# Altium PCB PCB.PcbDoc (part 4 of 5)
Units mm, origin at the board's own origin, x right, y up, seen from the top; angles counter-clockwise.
Board outline 101.6 x 53.34 mm, 6 copper layers (Top Layer, Int1 (GND), Int2, Int3, Int4 (GND), Bottom Layer), stack 1.625 mm thick; 228 components, 228 nets, 1016 pads, 995 vias.
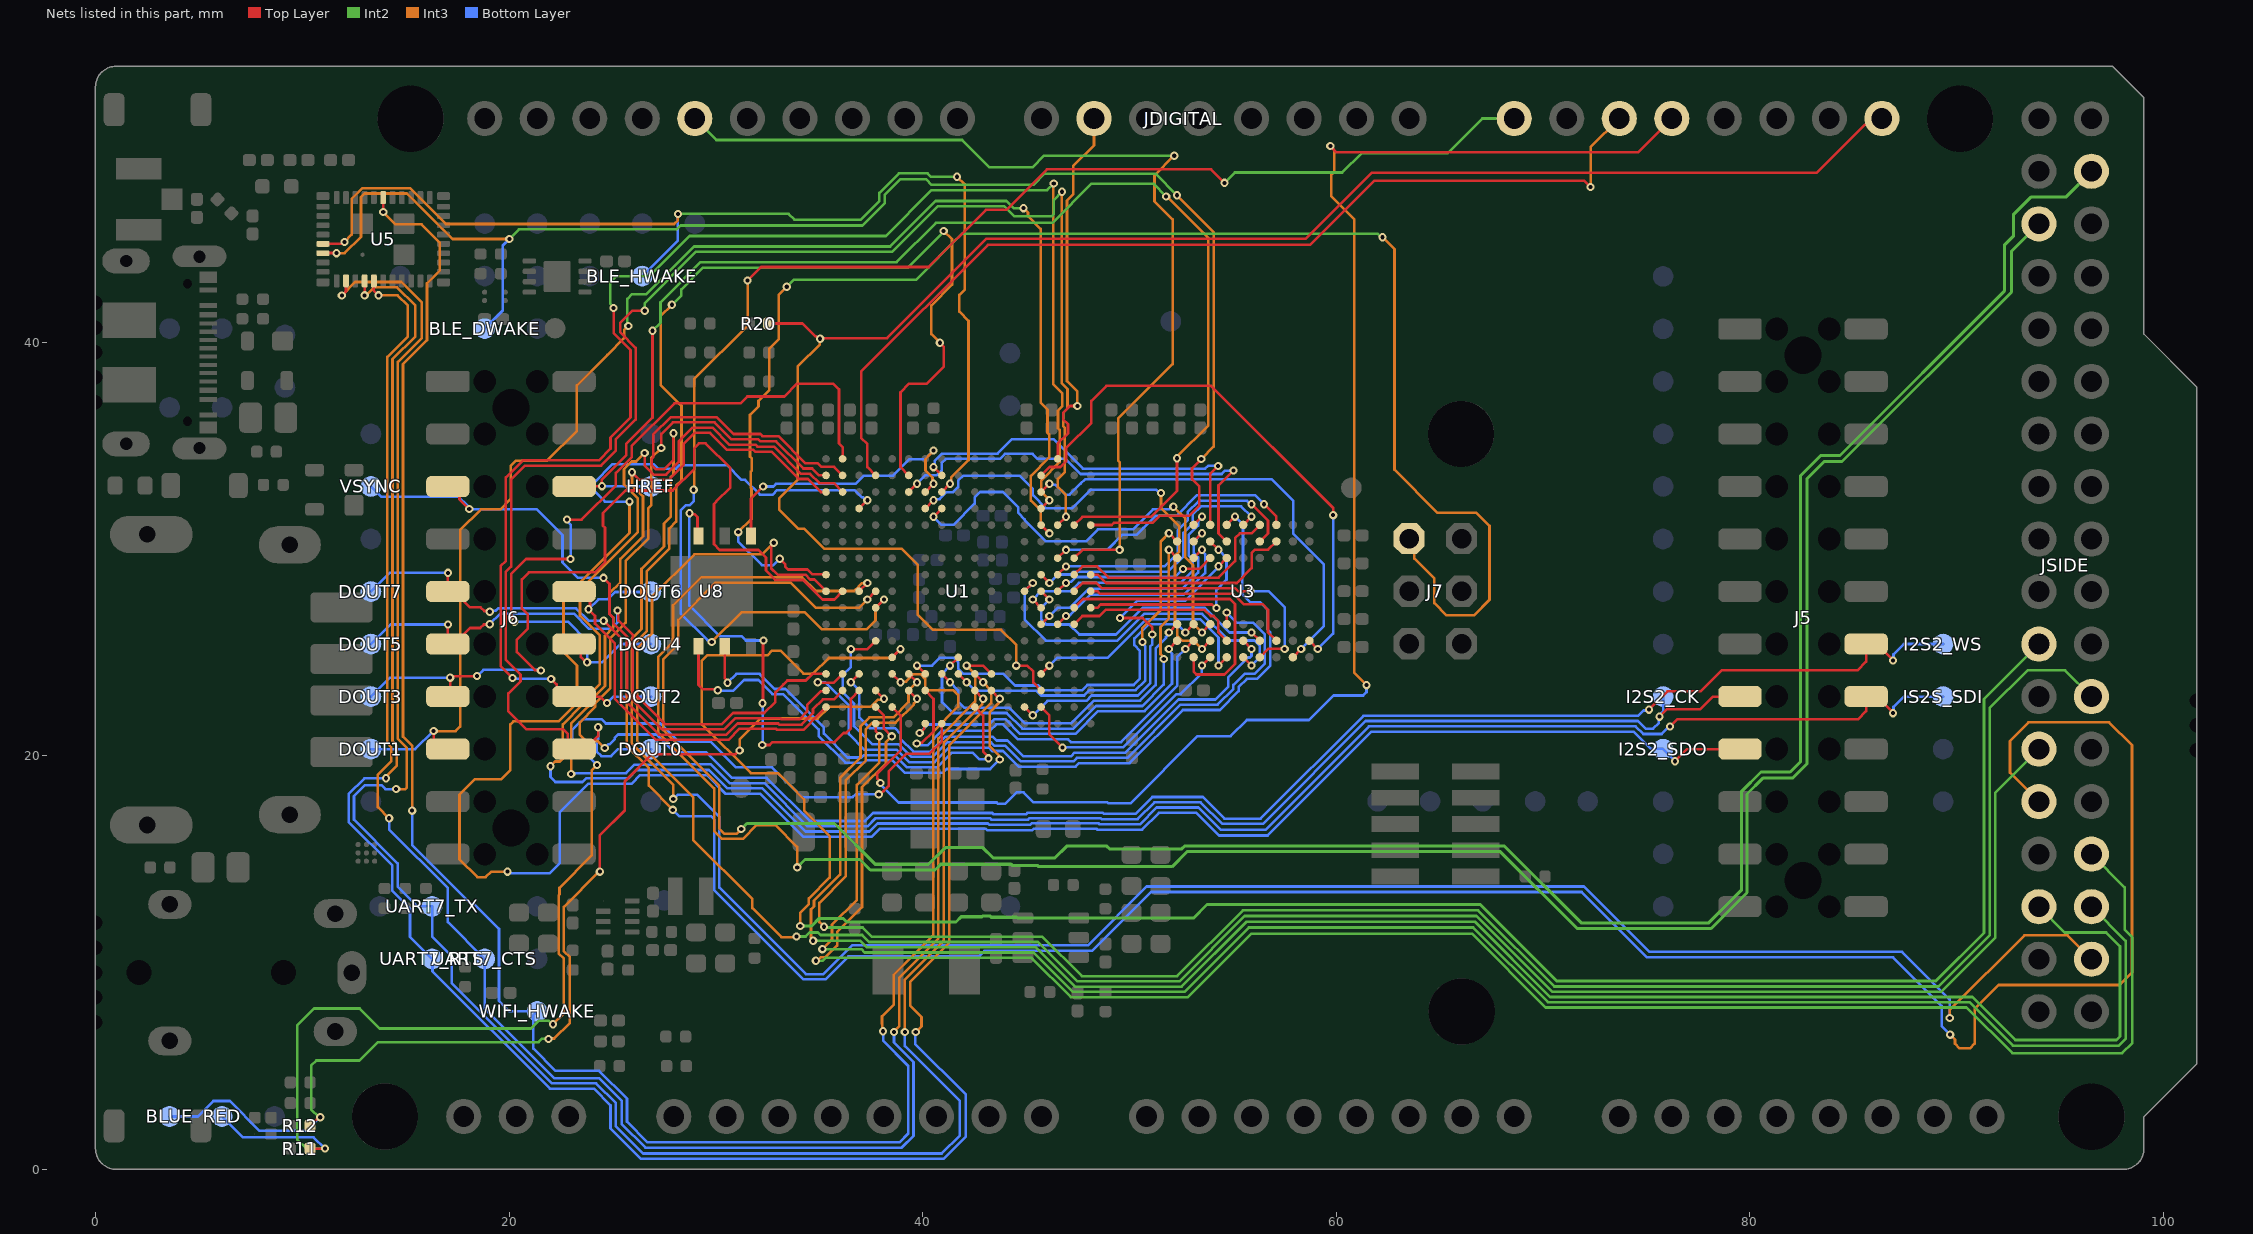
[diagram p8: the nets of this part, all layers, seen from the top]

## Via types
v1: diameter 0.4, hole 0.2, Top Layer to Bottom Layer, tented both sides, 995 vias

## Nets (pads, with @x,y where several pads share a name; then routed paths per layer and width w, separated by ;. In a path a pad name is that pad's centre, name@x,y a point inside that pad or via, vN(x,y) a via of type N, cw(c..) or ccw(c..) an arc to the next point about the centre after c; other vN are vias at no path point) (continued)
PD13: JDIGITAL.12 U1.R17 | length 18
  Top Layer w0.127: U1.R17@46.526,34.353 46.526,35.087 47.026,35.587 47.026,36.031 46.798,36.259 46.798,36.582 47.129,36.913 v1(47.482,36.913)
  Int3 w0.127: v1(47.482,36.913) 47.482,37.613 46.982,38.113 46.982,46.847 47.282,47.147 47.282,48.513 48.286,49.517 JDIGITAL.12@48.286,50.813
PD14_5: U1.P16 U3.A8 | length 27.1
  Top Layer w0.127: U1.P16@45.726,33.553 46.132,33.958 46.663,33.958 46.951,34.246 46.951,34.893 48.154,36.096 48.154,37.159 48.883,37.888 53.951,37.888 59.85,31.99 v1(59.85,31.633) ; U3.A8@58.704,25.56 v1(59.104,25.16)
  Bottom Layer w0.127: v1(59.104,25.16) 59.85,25.906 v1(59.85,31.633)
PD15_5: U1.P15 U3.B9 | length 22.1
  Top Layer w0.127: U1.P15@45.726,32.753 v1(46.126,33.153) ; U3.B9@57.904,24.76 v1(58.304,25.16)
  Bottom Layer w0.127: v1(46.126,33.153) 46.178,33.101 46.426,33.101 46.902,32.625 47.113,32.625 47.641,33.153 47.854,33.367 52.473,33.367 ; 52.473,33.366 56.881,33.366 57.913,32.334 57.913,30.747 59.404,29.257 59.404,26.26 v1(58.304,25.16)
PE0_5: U1.C4 U3.E8 | length 26.1
  Top Layer w0.127: v1(36.526,23.553) U1.C4@36.926,23.953 ; U3.E8@55.504,25.56 v1(55.904,25.16)
  Bottom Layer w0.127: v1(36.526,23.553) 36.936,23.144 36.936,21.84 37.441,21.334 38.658,21.334 38.936,21.056 38.936,20.817 39.555,20.198 40.374,20.198 41.098,20.921 43.384,20.921 43.571,20.734 44.104,20.734 44.859,19.98 47.187,19.98 47.354,20.147 49.799,20.147 52.372,22.72 54.161,22.72 54.773,23.332 54.773,23.781 55.742,24.75 55.829,24.75 55.904,24.825 v1(55.904,25.16)
PE1_5: U1.B4 U3.F1 | length 37.3
  Top Layer w0.127: v1(34.926,23.553) 34.951,23.528 35.702,23.528 U1.B4@36.126,23.953 ; U3.F1@54.704,31.16 v1(55.104,31.56)
  Bottom Layer w0.127: v1(34.926,23.553) 34.933,23.56 35.288,23.56 36.428,22.42 36.428,21.051 37.198,20.281 38.754,20.281 39.345,19.69 40.584,19.69 41.284,20.389 43.198,20.389 43.36,20.227 43.385,20.227 43.386,20.226 43.884,20.226 44.638,19.472 47.397,19.472 47.564,19.639 50.01,19.639 52.583,22.212 54.372,22.212 55.281,23.121 55.281,23.315 55.682,23.715 56.171,23.715 56.802,24.347 56.802,25.973 56.693,26.082 56.693,27.049 56.319,27.423 55.838,27.423 55.463,27.798 55.463,28.644 55.49,28.671 55.49,31.173 v1(55.104,31.56)
PE2_5: U1.C3 U8.3 | length 21.8
  Top Layer w0.127: v1(28.722,31.723) 28.774,31.67 28.982,31.67 29.113,31.54 29.113,30.671 U8.3@29.161,30.623 ; v1(32.242,20.515) 32.605,20.515 32.746,20.657 35.745,20.657 36.183,21.095 36.297,21.095 36.526,21.323 36.526,22.753 U1.C3@36.922,23.149 ; v1(32.259,22.539) 32.279,22.559 32.279,25.552 v1(32.3,25.572)
  Bottom Layer w0.127: v1(28.722,31.723) 28.722,27.257 30.206,25.773 31.252,25.773 31.453,25.572 v1(32.3,25.572) ; v1(32.242,20.515) 32.259,20.532 v1(32.259,22.539)
PE3: BLUE.X R12.2 U1.D3 | length 53.3
  Top Layer w0.127: R12.2@10.375,2.108 10.409,2.108 10.818,2.516 v1(10.867,2.516) ; v1(24.389,14.392) 24.389,16.154 25.594,17.36 25.594,18.745 26.919,20.071 30.958,20.071 31.138,20.25 v1(31.15,20.25) ; U1.D3@37.726,23.153 v1(38.126,22.753)
  Int2 w0.127: v1(10.867,2.516) 10.798,2.516 10.43,2.884 10.43,5.011 10.68,5.261 12.761,5.261 13.65,6.15 21.422,6.15 21.577,6.304 v1(21.904,6.304)
  Int3 w0.127: v1(21.904,6.304) 21.925,6.325 22.182,6.325 22.936,7.079 22.936,10.257 22.65,10.543 22.65,12.694 24.348,14.392 v1(24.389,14.392) ; v1(31.15,20.25) 31.15,20.792 32.157,21.798 34.922,21.798 35.486,22.362 37.488,22.362 37.827,22.701 38.075,22.701 v1(38.126,22.753)
  Bottom Layer w0.127: BLUE.X@3.582,2.553 4.953,2.553 5.7,3.3 6.5,3.3 7.938,1.862 10.213,1.862 v1(10.867,2.516)
PE4: JSIDE.30 U1.D2 | length 92.6
  Top Layer w0.127: U1.D2@37.726,22.353 38.126,21.953 38.126,21.314 v1(38.503,20.937)
  Int2 w0.127: v1(34.836,10.081) 35.163,10.081 35.31,10.227 45.26,10.227 47.165,8.323 52.823,8.323 55.897,11.397 66.555,11.397 70.128,7.825 90.48,7.825 92.689,5.615 98,5.615 98.5,6.115 98.5,11.215 98.126,11.589 98.126,13.633 JSIDE.30@96.52,15.239
  Int3 w0.127: v1(34.836,10.081) 34.909,10.081 35.082,10.254 35.312,10.254 35.868,10.811 35.868,11.473 37.068,12.673 37.068,18.476 38.226,19.635 38.226,20.66 v1(38.503,20.937)
PE5: JSIDE.32 U1.D1 | length 86.9
  Top Layer w0.127: U1.D1@37.726,21.553 37.726,21.185 37.903,21.008 v1(37.903,20.937)
  Int2 w0.127: v1(35.15,10.644) 37.036,10.644 37.199,10.481 45.366,10.481 47.27,8.577 52.658,8.577 55.775,11.693 66.619,11.693 70.233,8.079 90.617,8.079 92.72,5.976 97.84,5.976 98.177,6.312 98.177,11.042 JSIDE.32@96.52,12.699
  Int3 w0.127: v1(35.15,10.644) 35.614,11.109 35.614,11.829 36.814,13.029 36.814,18.581 37.903,19.671 v1(37.903,20.937)
PE6: JSIDE.21 U1.E5 | length 103.5
  Top Layer w0.127: U1.E5@38.526,24.753 v1(38.926,25.153)
  Int2 w0.15: v1(34.082,11.767) 34.631,11.767 34.995,12.131 36.149,12.131 36.322,11.958 41.609,11.958 41.863,12.211 42.868,12.211 42.914,12.258 43.247,12.258 43.317,12.188 44.536,12.188 44.579,12.144 53.095,12.144 53.752,12.801 66.964,12.801 70.652,9.113 89.005,9.113 91.322,11.429 91.322,22.74 JSIDE.21@93.98,25.399
  Int3 w0.127: v1(34.082,11.767) 34.082,12.409 34.492,12.818 34.492,13.098 35.5,14.106 35.5,16.109 34.271,17.338 34.271,17.888 33.933,18.226 33.933,18.236 33.109,19.059 33.099,19.059 33.001,19.158 31.691,19.158 29.311,21.537 29.311,24.591 29.576,24.856 32.5,24.856 32.723,25.079 33.127,25.079 34.236,23.97 34.708,23.97 35.461,24.723 38.496,24.723 v1(38.926,25.153)
PE7_5: U1.U9 U3.C8 | length 10.6
  Top Layer w0.127: U1.U9@48.126,27.953 48.445,27.953 48.562,27.836 55.017,27.836 55.522,27.331 56.423,27.331 56.699,27.055 56.699,25.964 U3.C8@57.104,25.56
PE8_5: U1.T9 U3.D9 | length 14.2
  Top Layer w0.127: U1.T9@47.326,27.953 47.726,28.353 48.217,28.353 48.404,28.353 48.667,28.09 55.122,28.09 55.253,27.96 v1(55.854,27.96) ; U3.D9@56.304,24.76 56.708,25.164 57.499,25.164 v1(57.504,25.16)
  Bottom Layer w0.127: v1(55.854,27.96) 56.723,27.96 57.512,27.171 57.512,25.168 v1(57.504,25.16)
PE9_5: U1.P9 U3.D8 | length 13.8
  Top Layer w0.127: U1.P9@45.726,27.953 v1(46.126,27.553) ; v1(55.904,25.96) U3.D8@56.304,25.56
  Bottom Layer w0.127: v1(46.126,27.553) 45.736,27.163 45.736,26.591 45.983,26.343 47.088,26.343 47.573,25.858 49.352,25.858 50.653,27.16 53.636,27.16 54.836,25.96 v1(55.904,25.96)
PE10_5: U1.N9 U3.E9 | length 17.1
  Top Layer w0.127: U1.N9@44.926,27.953 v1(45.326,28.353) ; U3.E9@55.504,24.76 v1(55.904,24.36)
  Bottom Layer w0.127: v1(45.326,28.353) 44.936,27.962 44.936,26.591 45.964,25.562 49.415,25.562 50.712,26.859 53.516,26.859 54.806,25.569 56.047,25.569 56.294,25.322 56.294,24.75 v1(55.904,24.36)
PE11_5: U1.P10 U3.E1 | length 13.6
  Top Layer w0.127: U1.P10@45.726,28.753 v1(46.126,28.353) ; U3.E1@55.504,31.16 v1(55.904,31.56)
  Bottom Layer w0.127: v1(46.126,28.353) 46.533,28.76 47.152,28.76 47.29,28.898 51.876,28.898 52.605,29.627 52.605,30.773 53.069,31.236 53.069,31.677 53.452,32.06 55.404,32.06 v1(55.904,31.56)
PE12_5: U1.R10 U3.D2 | length 14.1
  Top Layer w0.127: U1.R10@46.526,28.753 v1(46.926,29.153) ; v1(55.904,32.16) 56.699,31.364 56.699,30.755 U3.D2@56.304,30.36
  Bottom Layer w0.127: v1(46.926,29.153) 51.697,29.153 52.339,29.795 52.339,30.904 52.815,31.38 52.815,31.783 53.359,32.327 55.693,32.327 55.86,32.16 v1(55.904,32.16)
PE13_5: U1.T10 U3.D1 | length 11.1
  Top Layer w0.127: U1.T10@47.326,28.753 47.726,29.153 48.44,29.153 48.985,28.608 54.311,28.608 55.108,29.405 55.108,30.524 55.34,30.755 55.899,30.755 U3.D1@56.304,31.16
PE14_5: U1.U10 U3.C2 | length 10.4
  Top Layer w0.127: U1.U10@48.126,28.753 48.465,28.753 48.864,28.354 55.192,28.354 55.908,29.07 55.908,29.791 56.081,29.964 56.708,29.964 U3.C2@57.104,30.36
PE15_5: U1.R11 U3.C1 | length 12.7
  Top Layer w0.127: U1.R11@46.526,29.553 v1(46.926,29.953) ; v1(56.504,32.16) 57.104,31.56 U3.C1@57.104,31.16
  Bottom Layer w0.127: v1(46.926,29.953) 48.926,29.953 49.662,30.689 50.361,30.689 50.681,31.009 50.681,31.015 50.909,31.243 50.915,31.243 51.266,31.595 52.268,31.595 53.268,32.595 56.069,32.595 v1(56.504,32.16)
PF0_5: U1.G4 U3.H7 | length 18.1
  Top Layer w0.127: v1(39.726,24.353) U1.G4@40.126,23.953 ; v1(52.704,25.96) U3.H7@53.104,26.36
  Bottom Layer w0.127: v1(39.726,24.353) 40.449,24.353 40.839,24.743 41.488,24.743 41.728,24.504 41.728,24.199 41.967,23.96 43.904,23.96 44.466,23.397 45.593,23.397 45.828,23.162 47.703,23.162 47.961,23.42 50.199,23.42 50.505,23.726 50.505,25.072 50.236,25.341 50.236,25.665 50.549,25.978 ; 50.549,25.978 50.922,26.351 52.312,26.351 v1(52.704,25.96)
PF1_5: U1.G3 U3.H8 | length 20.2
  Top Layer w0.127: v1(39.717,20.588) 39.756,20.627 39.976,20.627 40.526,21.177 40.526,22.753 U1.G3@40.13,23.149 ; v1(52.704,25.16) U3.H8@53.104,25.56
  Bottom Layer w0.127: v1(39.717,20.588) 39.769,20.536 39.895,20.536 39.928,20.503 40.232,20.503 40.937,21.208 43.262,21.208 43.57,21.516 43.894,21.516 44.618,20.792 47.028,20.792 47.165,20.655 49.589,20.655 52.309,23.375 52.309,24.765 v1(52.704,25.16)
PF2_5: U1.G1 U3.J8 | length 16.7
  Top Layer w0.127: v1(39.855,21.1) 40.08,21.324 40.08,21.507 U1.G1@40.126,21.553 ; v1(51.904,25.16) U3.J8@52.304,25.56
  Bottom Layer w0.127: v1(39.855,21.1) 40.262,21.507 43.202,21.507 43.465,21.77 43.999,21.77 44.715,21.054 47.391,21.054 48.487,22.15 50.725,22.15 52.055,23.48 52.055,24.935 51.904,25.086 v1(51.904,25.16)
PF3_5: U1.H4 U3.J7 | length 15.8
  Top Layer w0.127: U1.H4@40.926,23.953 v1(41.326,23.553) ; v1(51.904,25.96) U3.J7@52.304,26.36
  Bottom Layer w0.127: v1(41.326,23.553) 41.717,23.162 41.717,22.61 42.007,22.32 44.184,22.32 44.942,21.562 47.181,21.562 48.276,22.658 50.515,22.658 51.267,23.411 51.267,25.191 51.768,25.692 51.768,25.75 51.904,25.886 v1(51.904,25.96)
PF4_5: U1.J5 U3.J3 | length 21.9
  Top Layer w0.127: v1(41.326,24.353) U1.J5@41.726,24.753 ; v1(51.904,29.96) U3.J3@52.304,29.56
  Int3 w0.127: v1(51.658,24.679) 51.658,24.753 51.498,24.912 51.498,26.219 51.904,26.624 v1(51.904,29.96)
  Bottom Layer w0.127: v1(41.326,24.353) 40.936,23.962 40.936,22.591 41.461,22.066 44.062,22.066 44.82,21.308 47.286,21.308 48.381,22.404 50.62,22.404 51.658,23.442 v1(51.658,24.679)
PF5_5: U1.J4 U3.J2 | length 18
  Top Layer w0.127: U1.J4@41.726,23.953 v1(42.126,23.553) ; v1(51.904,30.76) U3.J2@52.304,30.36
  Int3 w0.127: v1(50.626,25.503) 50.626,26.169 51.513,27.056 51.513,30.369 v1(51.904,30.76)
  Bottom Layer w0.127: v1(42.126,23.553) 42.536,23.143 45.488,23.143 45.723,22.908 47.808,22.908 48.066,23.166 50.304,23.166 50.759,23.621 50.759,25.296 50.626,25.429 v1(50.626,25.503)
PF6_5: U1.K2 U8.7 | length 19.9
  Top Layer w0.127: U8.7@30.431,25.283 30.431,23.74 30.567,23.604 v1(30.567,23.531) ; U1.K2@42.526,22.353 42.926,21.953 42.926,20.203 43.189,19.94 v1(43.189,19.871)
  Bottom Layer w0.127: v1(30.567,23.531) 30.997,23.961 32.111,23.961 32.844,23.228 33.362,23.228 35.221,21.369 35.221,21.066 36.372,19.915 37.044,19.915 37.156,20.027 38.64,20.027 39.231,19.436 40.69,19.436 41.389,20.135 42.431,20.135 42.735,19.83 43.149,19.83 v1(43.189,19.871)
PF7: U1.K3 U5.2 UART7_TX.X | length 97.1
  Top Layer w0.127: v1(11.914,42.258) 12.115,42.458 U5.2@12.115,42.96 ; U1.K3@42.526,23.153 v1(42.926,22.753)
  Int3 w0.127: v1(11.914,42.258) 12.562,42.905 14.795,42.905 15.78,41.92 15.78,40.197 14.62,39.036 14.62,20.816 15.058,20.378 15.058,18.459 14.983,18.384 v1(14.54,18.384) ; v1(39.139,6.634) 39.139,9.167 41.025,11.054 41.025,20.641 42.882,22.499 42.882,22.709 v1(42.926,22.753)
  Bottom Layer w0.127: v1(14.54,18.384) 14.021,18.384 13.83,18.575 13.025,18.575 12.5,18.049 12.5,16.907 14.613,14.794 14.613,13.676 15.577,12.713 UART7_TX.X@16.282,12.713 16.282,11.247 17.222,10.307 17.222,9.008 22.075,4.154 24.21,4.154 25.165,3.199 25.165,2.079 26.479,0.765 40.918,0.765 41.794,1.642 41.794,3.306 39.139,5.961 v1(39.139,6.634)
PF8: U1.K4 U5.4 UART7_RTS.X | length 96
  Top Layer w0.127: v1(13.015,42.26) U5.4@13.015,42.96 ; U1.K4@42.526,23.953 v1(42.926,23.553)
  Int3 w0.127: v1(13.015,42.26) 13.089,42.26 13.48,42.651 14.581,42.651 15.466,41.767 15.466,40.274 14.366,39.174 14.366,20.711 14.564,20.513 14.564,19.508 14.155,19.1 14.155,19.09 14.048,18.983 v1(14.048,18.909) ; v1(39.666,6.634) 39.947,6.916 39.947,7.362 39.393,7.916 39.393,9.062 41.279,10.948 41.279,20.501 43.317,22.538 43.317,23.162 v1(42.926,23.553)
  Bottom Layer w0.127: v1(14.048,18.909) 13.001,18.909 12.246,18.154 12.246,16.802 14.359,14.689 14.359,13.463 15.21,12.612 15.21,11.244 16.298,10.157 16.298,9.573 21.97,3.9 24.1,3.9 24.908,3.092 24.908,1.972 26.372,0.508 41.02,0.508 42.092,1.58 42.092,3.608 39.637,6.063 39.637,6.605 v1(39.666,6.634)
PF9: U1.L4 U5.5 UART7_CTS.X | length 90
  Top Layer w0.127: U5.5@13.465,42.96 13.465,42.481 v1(13.686,42.26) ; v1(42.126,24.353) 42.926,24.353 U1.L4@43.326,23.953
  Int3 w0.127: v1(13.686,42.26) 14.613,42.26 15.109,41.765 15.109,40.276 14.112,39.279 14.112,20.606 14.31,20.408 14.31,19.732 13.658,19.08 13.658,17.517 v1(14.2,16.975) ; v1(38.612,6.634) 38.612,6.66 38.874,6.921 38.874,9.277 40.76,11.163 40.76,20.835 42.536,22.61 42.536,23.943 v1(42.126,24.353)
  Bottom Layer w0.127: v1(14.2,16.975) 14.2,16.433 17.037,13.596 17.037,11.957 UART7_CTS.X@18.822,10.173 18.822,7.767 22.181,4.408 24.353,4.408 25.446,3.315 25.446,2.195 26.595,1.046 38.989,1.046 39.557,1.614 39.557,5.184 38.612,6.129 v1(38.612,6.634)
PF10_5: U1.L3 U8.6 | length 23
  Top Layer w0.127: U8.6@29.161,25.283 29.161,24.158 29.161,23.424 29.365,23.22 30.038,23.22 v1(30.09,23.167) ; U1.L3@43.326,23.153 v1(43.726,22.753)
  Int3 w0.127: v1(43.726,19.815) 43.674,19.867 43.674,20.027 43.245,20.456 43.245,22.108 43.674,22.536 43.674,22.701 v1(43.726,22.753)
  Bottom Layer w0.127: v1(30.09,23.167) 30.118,23.14 30.835,23.14 31.358,23.663 32.05,23.663 32.739,22.974 33.257,22.974 34.967,21.264 34.967,20.961 36.267,19.661 37.178,19.661 37.29,19.773 38.534,19.773 39.126,19.182 40.986,19.182 41.158,19.354 43.265,19.354 v1(43.726,19.815)
PF11_5: U1.T7 U3.F8 | length 8.6
  Top Layer w0.127: U1.T7@47.326,26.353 47.726,26.753 48.547,26.753 48.85,27.056 53.636,27.056 53.937,26.755 54.068,26.755 54.299,26.524 54.299,25.964 U3.F8@54.704,25.56
PF12_5: U1.R7 U3.H3 | length 9.9
  Top Layer w0.127: U1.R7@46.526,26.353 v1(46.926,26.753) ; U3.H3@53.104,29.56 v1(53.504,29.96)
  Bottom Layer w0.127: v1(46.926,26.753) 46.978,26.805 47.129,26.805 48.103,27.779 52.61,27.779 53.659,28.828 53.659,29.749 53.504,29.904 v1(53.504,29.96)
PF13_5: U1.P7 U3.H2 | length 11.4
  Top Layer w0.127: U1.P7@45.726,26.353 v1(46.126,26.753) ; U3.H2@53.104,30.36 v1(53.504,30.76)
  Bottom Layer w0.127: v1(46.126,26.753) 46.533,27.16 47.124,27.16 48.03,28.066 52.538,28.066 53.326,28.854 53.326,29.586 53.113,29.798 53.113,30.369 v1(53.504,30.76)
PF14_5: U1.P8 U3.H1 | length 12.4
  Top Layer w0.127: v1(45.326,27.553) U1.P8@45.726,27.153 ; U3.H1@53.104,31.16 v1(53.504,31.56)
  Bottom Layer w0.127: v1(45.326,27.553) 45.726,27.953 47.149,27.953 47.557,28.361 52.474,28.361 53.061,28.948 53.061,29.491 52.859,29.693 52.859,30.668 53.323,31.131 53.323,31.316 53.504,31.497 v1(53.504,31.56)
PF15_5: U1.R9 U3.G3 | length 8
  Top Layer w0.127: U1.R9@46.526,27.953 v1(46.926,28.353) ; v1(52.593,29.032) 53.376,29.032 U3.G3@53.904,29.56
  Bottom Layer w0.127: v1(46.926,28.353) 46.978,28.405 47.169,28.405 47.408,28.644 52.204,28.644 v1(52.593,29.032)
PG0_5: U1.T8 U3.H9 | length 13.9
  Top Layer w0.127: U1.T8@47.326,27.153 47.751,27.577 54.855,27.577 55.103,27.33 55.103,24.441 54.587,23.926 53.238,23.926 53.104,24.06 U3.H9@53.104,24.76
PG1_5: U1.U8 U3.G2 | length 10
  Top Layer w0.127: U1.U8@48.126,27.153 48.45,27.153 48.607,27.31 53.994,27.31 54.161,27.143 v1(54.205,27.143) ; U3.G2@53.904,30.36 v1(54.304,29.96)
  Bottom Layer w0.127: v1(54.205,27.143) 54.205,28.025 54.694,28.514 54.694,29.569 v1(54.304,29.96)
PG2_5: U1.H16 U3.G1 | length 18.7
  Top Layer w0.127: v1(40.526,33.953) U1.H16@40.926,33.553 ; U3.G1@53.904,31.16 53.904,33.626 v1(54.289,34.011)
  Bottom Layer w0.127: v1(40.526,33.953) 40.578,34.005 40.578,34.253 40.935,34.61 43.624,34.61 44.323,35.309 46.316,35.309 47.749,33.876 53.665,33.876 53.805,34.016 54.283,34.016 v1(54.289,34.011)
PG3: BLE_HWAKE.X U1.H15 U5.38 | length 55.2
  Top Layer w0.127: U5.38@11,44.75 11.872,44.75 11.963,44.841 v1(12.037,44.841) ; U1.H15@40.926,32.753 v1(41.326,33.153)
  Int2 w0.127: v1(28.165,46.2) 33.515,46.2 33.797,45.918 37.008,45.918 37.906,46.816 37.906,47.22 38.849,48.163 40.238,48.163 40.407,47.994 v1(41.664,47.994)
  Int3 w0.127: v1(12.037,44.841) 12.388,45.192 12.388,46.919 12.912,47.442 15.212,47.442 16.945,45.709 27.983,45.709 28.165,45.891 v1(28.165,46.2) ; v1(41.326,33.153) 41.378,33.205 41.378,33.453 42.216,34.291 42.216,41.025 41.77,41.471 41.77,42.277 42.036,42.543 42.036,47.622 v1(41.664,47.994)
  Bottom Layer w0.127: BLE_HWAKE.X@26.442,43.193 28.165,44.916 v1(28.165,46.2)
PG4_5: U1.H14 U3.G7 | length 22.2
  Top Layer w0.127: v1(40.526,31.553) U1.H14@40.926,31.953 ; v1(53.504,25.96) U3.G7@53.904,26.36
  Int3 w0.127: v1(52.122,32.036) 52.698,31.46 52.698,29.592 53.075,29.215 53.075,26.389 v1(53.504,25.96)
  Bottom Layer w0.127: v1(40.526,31.553) 40.917,31.162 41.488,31.162 42.517,32.191 42.517,32.496 42.774,32.753 43.878,32.753 44.626,32.005 44.626,31.741 44.936,31.432 44.936,31.391 45.964,30.362 47.888,30.362 48.469,30.943 50.166,30.943 51.135,31.912 51.924,31.912 52.048,32.036 v1(52.122,32.036)
PG5_5: U1.G14 U3.G8 | length 22.9
  Top Layer w0.127: U1.G14@40.126,31.953 v1(40.526,32.353) ; v1(53.504,25.16) U3.G8@53.904,25.56
  Int3 w0.127: v1(51.526,32.703) 51.526,31.97 52.408,31.087 52.408,29.885 52.202,29.679 52.202,26.334 52.313,26.223 52.313,25.798 52.561,25.55 53.113,25.55 v1(53.504,25.16)
  Bottom Layer w0.127: v1(40.526,32.353) 40.578,32.405 40.826,32.405 41.164,32.743 41.469,32.743 41.717,32.991 41.717,33.296 41.964,33.543 44.688,33.543 45.326,32.905 45.326,32.601 45.964,31.962 46.298,31.962 47.215,31.962 48.111,32.859 51.297,32.859 51.452,32.703 v1(51.526,32.703)
PG6_5: U1.G15 U8.1 | length 14.1
  Top Layer w0.127: U8.1@31.701,30.623 31.701,31.748 ; 31.7,31.748 31.7,32.431 v1(32.286,33.017) ; U1.G15@40.126,32.753 v1(40.526,33.153)
  Int3 w0.127: v1(40.526,33.153) 40.474,33.205 40.474,33.453 40.136,33.791 40.136,34.347 40.278,34.489 40.278,34.504 v1(40.526,34.753)
  Bottom Layer w0.127: v1(32.286,33.017) 32.785,33.017 32.91,33.142 36.763,33.142 37.164,33.543 38.573,33.543 39.373,34.343 40.117,34.343 v1(40.526,34.753)
PG7: JSIDE.34 U1.F16 | length 136.9
  Top Layer w0.127: U1.F16@39.326,33.553 38.926,33.953 38.926,37.571 39.343,37.988 40.201,37.988 41.016,38.803 41.016,39.782 v1(40.831,39.969) v1(40.831,39.969)
  Int2 w0.127: v1(27.873,41.804) 28.329,42.26 28.329,42.541 29.387,43.599 39.283,43.599 41.016,45.331 v1(41.016,45.378)
  Int3 w0.127: 26.301,25.663 25.936,25.298 25.936,20.578 27.942,18.573 v1(27.942,17.913) ; 26.301,25.664 26.66,26.022 26.66,28.928 27.748,30.015 27.748,30.996 28.077,31.326 28.077,33.054 28.339,33.316 28.339,36.914 27.328,37.925 27.328,41.259 v1(27.873,41.804) ; v1(40.831,39.969) 40.416,40.384 40.416,41.778 41.416,42.778 41.416,44.978 v1(41.016,45.378) ; v1(89.666,7.313) 89.666,7.699 93.276,11.31 95.369,11.31 JSIDE.34@96.52,10.159
  Bottom Layer w0.127: v1(27.942,17.913) 27.961,17.913 28.152,18.105 29.102,18.105 30.168,17.038 30.168,13.618 34.35,9.437 35.199,9.437 36.593,10.83 47.986,10.83 50.833,13.677 71.978,13.677 75.138,10.516 87.357,10.516 89.666,8.207 v1(89.666,7.313)
PG8_5: U1.F15 U3.F2 | length 21
  Top Layer w0.127: U1.F15@39.326,32.753 v1(39.726,33.153) ; U3.F2@54.704,30.36 54.308,30.755 54.308,33.07 v1(55.026,33.788)
  Bottom Layer w0.127: v1(39.726,33.153) 40.136,33.562 40.688,33.562 40.917,33.791 40.917,34.155 41.117,34.356 43.729,34.356 43.971,34.597 45.32,34.597 45.562,34.356 46.911,34.356 47.644,33.622 52.576,33.622 52.579,33.62 54.456,33.62 54.624,33.788 v1(55.026,33.788)
PG9: J7.1 U1.A10 | length 76.2
  Top Layer w0.127: v1(33.093,29.526) 33.354,29.265 33.354,29.146 33.494,29.006 34.432,29.006 34.665,28.772 35.307,28.772 U1.A10@35.326,28.753
  Int2 w0.127: v1(33.429,42.68) 33.764,43.014 39.667,43.014 41.894,45.241 61.999,45.241 62.168,45.073 v1(62.242,45.073)
  Int3 w0.127: v1(31.081,30.809) 31.721,31.449 31.721,32.942 31.683,32.979 31.683,33.738 31.736,33.79 31.736,34.378 31.652,34.462 31.652,36.481 32.062,36.891 32.062,37.156 32.584,37.677 32.584,39.689 33.047,40.152 33.047,42.297 v1(33.429,42.68) ; v1(62.242,45.073) 62.817,44.497 62.817,33.831 64.903,31.745 66.776,31.745 67.41,31.111 67.41,27.541 66.652,26.783 65.331,26.783 64.742,27.373 64.742,28.573 63.779,29.535 63.779,30.239 J7.1@63.526,30.493
  Bottom Layer w0.127: v1(31.081,30.809) 31.081,30.358 32.228,29.211 32.777,29.211 v1(33.093,29.526)
PG10: JSIDE.25 U1.A9 | length 104.7
  Top Layer w0.127: v1(32.8,30.3) 32.8,30.226 32.678,30.104 32.678,29.059 32.986,28.752 34.327,28.752 34.56,28.518 34.761,28.518 U1.A9@35.326,27.953
  Int2 w0.127: v1(33.896,11.258) 34.344,11.258 34.539,11.452 34.932,11.452 35.057,11.327 37.071,11.327 37.409,10.989 45.576,10.989 47.48,9.085 52.412,9.085 55.574,12.247 66.783,12.247 70.443,8.587 89.263,8.587 91.874,11.198 91.874,18.213 JSIDE.25@93.98,20.319
  Int3 w0.127: 26.555,25.558 26.19,25.193 26.19,20.707 28.898,17.999 28.898,15.934 31.765,13.067 31.765,12.63 33.172,11.222 33.86,11.222 v1(33.896,11.258) ; 26.555,25.559 26.914,25.917 26.914,27.692 28.959,29.737 32.237,29.737 v1(32.8,30.3)
PG11: DOUT3.X J6.13 U1.B9 | length 42.4
  Top Layer w0.127: J6.13@17.042,22.859 17.151,22.967 v1(17.151,23.776) 17.225,23.85 v1(18.45,23.85) ; v1(21.537,24.12) 21.523,24.134 21.252,24.134 20.374,25.012 20.374,25.612 20.905,26.142 20.905,26.831 20.622,27.114 20.622,28.523 20.965,28.867 24.151,28.867 24.637,29.353 24.637,31.023 24.542,31.118 24.542,31.734 25.636,32.827 27.91,32.827 28.958,33.876 28.958,34.875 29.187,35.104 29.511,35.104 30.699,33.916 30.699,32.976 30.017,32.294 30.017,32.276 29.909,32.169 29.909,30.225 30.185,29.949 32.053,29.949 32.424,29.577 32.424,28.954 32.881,28.498 34.221,28.498 35.166,27.553 35.726,27.553 U1.B9@36.126,27.953
  Bottom Layer w0.127: DOUT3.X@13.322,22.859 14.239,23.776 v1(17.151,23.776) ; v1(18.45,23.85) 18.752,24.152 21.505,24.152 v1(21.537,24.12)
PG12: JSIDE.5 U1.C9 | length 117.7
  Top Layer w0.127: U1.C9@36.926,27.953 v1(37.326,28.353)
  Int2 w0.15: v1(33.933,14.6) 34.312,14.98 36.966,14.98 37.473,14.473 40.599,14.473 40.876,14.75 41.882,14.75 ; 41.883,14.751 44.28,14.751 44.35,14.681 45.568,14.681 45.612,14.637 52.062,14.637 52.784,15.359 67.932,15.359 71.65,11.641 78.129,11.641 79.866,13.378 79.866,14.309 79.866,18.147 80.631,18.913 82.066,18.913 82.755,19.602 82.755,33.382 83.597,34.224 84.459,34.224 92.654,42.419 92.654,44.392 JSIDE.5@93.98,45.719
  Int3 w0.127: v1(33.933,14.6) 33.933,15.588 32.88,16.641 31.973,16.641 31.309,15.977 30.292,15.977 29.914,16.355 29.914,18.42 27.206,21.128 27.206,24.772 27.571,25.137 27.93,25.496 27.93,27.271 29.285,28.626 34.173,28.626 34.836,27.963 36.688,27.963 36.917,28.191 36.917,28.2 37.049,28.332 37.305,28.332 v1(37.326,28.353)
PG13: JSIDE.4 U1.D9 | length 120.4
  Top Layer w0.127: v1(37.326,27.553) U1.D9@37.726,27.953
  Int2 w0.15: v1(31.23,16.451) 31.5,16.721 35.739,16.721 37.709,14.75 40.282,14.75 41.086,15.554 42.906,15.554 43.398,15.062 46.398,15.062 46.964,15.628 48.904,15.628 49.037,15.495 52.528,15.495 52.669,15.636 68.125,15.636 71.843,11.918 78.014,11.918 79.589,13.493 79.589,18.262 80.54,19.213 81.949,19.213 82.455,19.718 82.455,33.548 83.426,34.519 84.363,34.519 92.306,42.463 92.306,44.682 92.742,45.118 92.742,46.164 93.59,47.013 95.274,47.013 JSIDE.4@96.52,48.259
  Int3 w0.127: 27.825,25.032 27.46,24.667 27.46,21.233 30.168,18.525 30.168,16.46 30.397,16.231 31.01,16.231 v1(31.23,16.451) ; 27.825,25.032 28.184,25.391 28.184,26.569 29.987,28.372 33.612,28.372 34.821,27.162 36.936,27.162 v1(37.326,27.553)
PG14: JDIGITAL.19 U1.D8 | length 71.3
  Top Layer w0.127: v1(31.534,42.977) 32.189,43.632 40.287,43.632 43.052,46.397 44.05,46.397 46.005,48.352 53.948,48.352 v1(54.6,47.7) ; U1.D8@37.726,27.153 v1(38.126,27.553)
  Int2 w0.127: v1(54.6,47.7) 55.1,48.2 60.288,48.2 61.234,49.146 65.394,49.146 67.06,50.813 JDIGITAL.19@68.606,50.813
  Int3 w0.127: v1(28.925,32.859) 28.952,32.886 28.952,38.214 31.543,40.805 31.543,42.968 v1(31.534,42.977) ; v1(29.8,25.5) 31.232,26.932 34.301,26.932 35.125,26.108 37.282,26.108 37.717,26.543 37.717,27.143 v1(38.126,27.553)
  Bottom Layer w0.127: v1(28.925,32.859) 28.925,32.299 28.739,32.113 28.56,32.113 28.295,31.849 28.295,26.883 29.59,25.588 29.638,25.588 29.726,25.5 v1(29.8,25.5)
PG15_5: U1.D6 U3.F7 | length 33
  Top Layer w0.127: v1(36.526,25.153) 37.326,25.153 U1.D6@37.726,25.553 ; U3.F7@54.704,26.36 v1(54.704,26.925)
  Bottom Layer w0.127: v1(36.526,25.153) 36.526,24.285 36.136,23.895 36.136,23.072 36.682,22.526 36.682,21.429 37.564,20.546 38.847,20.546 39.45,19.944 40.479,19.944 41.178,20.643 42.641,20.643 43.303,20.643 43.466,20.48 43.999,20.48 44.754,19.726 47.292,19.726 47.459,19.893 49.904,19.893 52.478,22.466 54.266,22.466 55.027,23.227 55.027,23.42 55.577,23.969 56.066,23.969 56.548,24.452 56.548,25.868 55.991,26.425 55.204,26.425 v1(54.704,26.925)
PH2_5: U1.N2 U3.F3 | length 17.8
  Top Layer w0.127: U1.N2@44.926,22.353 v1(45.326,21.953) ; v1(49.545,26.66) 50.639,26.66 51.104,26.195 v1(51.104,25.86) ; v1(54.304,29.16) U3.F3@54.704,29.56
  Bottom Layer w0.127: v1(45.326,21.953) 46.028,22.654 47.913,22.654 48.171,22.912 50.409,22.912 51.013,23.516 51.013,25.296 51.104,25.387 v1(51.104,25.86) ; v1(49.545,26.66) 50.373,27.488 52.679,27.488 54.304,29.113 v1(54.304,29.16)
PH3_5: U1.P2 U3.G9 | length 11.5
  Top Layer w0.127: U1.P2@45.726,22.353 46.117,21.962 46.117,21.039 v1(46.767,20.388) ; v1(53.504,24.36) U3.G9@53.904,24.76
  Bottom Layer w0.127: v1(46.767,20.388) 46.779,20.401 49.694,20.401 52.267,22.974 52.47,22.974 53.504,24.008 v1(53.504,24.36)
PH4: JDIGITAL.26 R20.1 U1.P3 | length 86.2
  Top Layer w0.127: R20.1@32.56,40.898 34.191,40.898 34.811,40.279 34.85,40.279 34.969,40.159 v1(35.043,40.159) ; v1@35.043,40.188 38.28,40.188 43.092,45 58.528,45 61.722,48.194 83.243,48.194 85.561,50.512 86.085,50.512 JDIGITAL.26@86.386,50.813 ; v1(44.526,24.353) 45.057,24.353 45.351,24.06 45.351,23.528 U1.P3@45.726,23.153
  Int3 w0.127: v1(35.043,40.159) 35.025,40.141 35.025,39.896 33.964,38.835 33.964,33.348 33.064,32.448 33.064,31.896 33.977,30.983 34.264,30.983 35.235,30.013 38.966,30.013 39.766,29.213 39.766,26.813 40.493,26.085 43.793,26.085 44.526,25.352 v1(44.526,24.353)
PH5_5: U1.P4 U3.F9 | length 12
  Top Layer w0.127: U1.P4@45.726,23.953 v1(46.126,24.353) ; v1(54.304,24.36) U3.F9@54.704,24.76
  Bottom Layer w0.127: v1(46.126,24.353) 46.517,24.743 48.955,24.743 50.817,26.605 53.41,26.605 54.304,25.712 v1(54.304,24.36)
PH6: JDIGITAL.5 U1.T11 | length 47.7
  Top Layer w0.127: U1.T11@47.326,29.553 47.726,29.953 v1(49.526,29.953)
  Int2 w0.127: JDIGITAL.5@28.982,50.813 30.022,49.772 41.906,49.772 43.225,48.453 45.306,48.453 45.866,49.013 v1(52.166,49.013)
  Int3 w0.127: v1(49.526,29.953) 49.526,34.198 49.467,34.257 49.467,36.318 52.087,38.938 52.087,45.931 51.211,46.807 51.211,48.058 v1(52.166,49.013)
PH7: BLE_DWAKE.X U1.U13 U5.39 | length 73.5
  Top Layer w0.127: U1.U13@48.126,31.153 49.135,31.153 49.246,31.263 51.118,31.263 51.449,31.595 52.868,31.595 53.376,32.103 53.376,33.026 53.025,33.376 53.025,33.898 v1(53.473,34.345)
  Top Layer w0.15: U5.39@11,44.3 v1(11.65,44.3)
  Int2 w0.127: v1(20.013,44.988) 20.48,45.455 28.104,45.455 28.291,45.642 37.091,45.642 38.16,46.711 38.16,47.115 38.914,47.868 40.174,47.868 40.438,47.604 45.357,47.604 45.895,48.142 51.258,48.142 v1(52.3,47.1)
  Int3 w0.127: v1(11.65,44.3) 12.048,44.3 12.842,45.093 12.842,47.013 13.017,47.188 15.066,47.188 17.266,44.988 v1(20.013,44.988) ; v1(52.3,47.1) 52.3,47.085 54.07,45.315 54.07,34.943 v1(53.473,34.345)
  Bottom Layer w0.127: BLE_DWAKE.X@18.822,40.653 19.694,41.525 19.694,44.67 v1(20.013,44.988)
PH8: HREF.X J6.6 U1.T13 | length 62.3
  Top Layer w0.127: J6.6@23.142,33.019 23.689,33.019 23.706,33.035 v1(24.491,33.035) 24.491,33.352 25.666,34.528 25.666,35.074 26.937,36.345 v1(26.937,40.55) ; U1.T13@47.326,31.153 47.726,31.553 51.048,31.553 52.301,32.806 v1(52.301,34.386)
  Int2 w0.127: v1(26.937,40.55) 27.321,40.934 27.321,41.924 29.261,43.864 38.743,43.864 40.648,45.768 46.282,45.768 48.174,47.66 51.159,47.66 v1(51.776,47.043)
  Int3 w0.127: v1(51.776,47.043) 51.805,47.043 53.816,45.032 53.816,35.974 52.301,34.46 v1(52.301,34.386)
  Bottom Layer w0.127: v1(24.491,33.035) 26.845,33.035 HREF.X@26.862,33.019
PH9: DOUT0.X J6.16 U1.R13 | length 76.5
  Top Layer w0.127: v1(24.308,21.377) 24.308,20.944 23.682,20.319 22.842,20.319 22.846,20.323 22.846,21.054 22.628,21.272 20.836,21.272 19.963,22.145 19.963,23.007 20.555,23.6 20.555,23.923 19.846,24.632 19.846,28.9 20.097,29.151 20.097,33.351 20.776,34.029 24.45,34.029 25.158,34.738 25.158,35.285 26.125,36.251 26.125,39.723 25.379,40.469 25.379,40.939 25.958,41.518 v1(26.562,41.518) ; U1.R13@46.526,31.153 v1(46.926,31.553)
  Int2 w0.127: v1(26.562,41.518) 26.562,41.882 29.051,44.372 38.533,44.372 40.729,46.568 43.946,46.568 44.43,46.084 45.678,46.084 45.68,46.082 46.229,46.082 46.342,46.196 46.342,46.874 v1(46.742,47.273)
  Int3 w0.127: v1(46.742,47.273) 46.728,47.259 46.728,38.007 47.002,37.733 47.002,36.786 46.798,36.582 46.798,35.935 46.879,35.854 46.879,33.721 46.536,33.378 46.536,32.991 46.926,32.601 v1(46.926,31.553)
  Bottom Layer w0.127: v1(24.308,21.377) 24.308,20.793 24.233,20.719 24.233,20.209 24.462,19.98 24.928,19.98 25.267,20.319 DOUT0.X@26.862,20.319
PH10: DOUT1.X J6.15 U1.P13 | length 70.6
  Top Layer w0.127: v1(16.355,21.191) 16.355,20.751 16.786,20.319 J6.15@17.042,20.319 J6.15@17.227,20.319 ; U1.P13@45.726,31.153 v1(46.126,30.753)
  Int2 w0.127: v1(25.769,40.777) 25.72,40.826 25.72,42.092 25.949,42.32 26.64,42.32 28.946,44.626 38.427,44.626 40.624,46.822 44.051,46.822 44.397,46.476 v1(44.88,46.476)
  Int3 w0.127: v1(16.355,21.191) 17.416,21.191 17.634,21.41 17.634,30.91 18.636,31.912 19.574,31.912 20.074,32.412 20.074,34.012 20.331,34.268 21.831,34.268 23.274,35.712 23.274,37.903 24.756,39.385 25.567,40.196 25.567,40.575 v1(25.769,40.777) ; v1(44.88,46.476) 45.095,46.262 45.095,46.091 45.708,45.479 45.708,37.072 46.036,36.744 46.036,35.619 46.117,35.539 46.117,34.414 45.228,33.525 45.228,32.34 45.717,31.851 45.717,31.162 v1(46.126,30.753)
  Bottom Layer w0.127: DOUT1.X@13.322,20.319 15.462,20.319 16.335,21.191 v1(16.355,21.191)
PH11: DOUT2.X J6.14 U1.P14 | length 71.8
  Top Layer w0.127: v1(20.165,23.761) 19.592,24.334 19.592,29.166 19.843,29.417 19.843,33.456 20.67,34.283 24.344,34.283 24.904,34.843 24.904,35.39 25.871,36.356 25.871,39.618 25.055,40.434 v1(25.055,41.65) ; v1(22.036,23.708) 22.301,23.443 22.301,23.291 22.733,22.859 J6.14@22.842,22.859 ; J6.14@23.142,22.859 24.398,22.859 24.706,22.55 v1(24.731,22.55) ; U1.P14@45.726,31.953 v1(46.126,32.353)
  Int2 w0.127: v1(25.055,41.65) 25.055,41.691 24.889,41.856 24.889,42.875 25.204,43.191 26.792,43.191 28.735,45.134 38.217,45.134 40.433,47.35 46.019,47.35 v1(46.342,47.673)
  Int3 w0.127: v1(46.126,32.353) 45.736,32.744 45.736,33.315 46.625,34.204 46.625,35.749 46.544,35.83 46.544,36.687 46.748,36.892 46.748,37.53 46.308,37.97 46.308,47.639 v1(46.342,47.673)
  Bottom Layer w0.127: v1(20.165,23.761) 20.197,23.729 22.014,23.729 v1(22.036,23.708) ; v1(24.731,22.55) 25.04,22.859 DOUT2.X@26.862,22.859
PH13: JDIGITAL.21 U1.D16 | length 48.4
  Top Layer w0.127: U1.D16@37.726,33.553 37.326,33.953 37.326,35.075 37.03,35.371 37.03,38.579 43.151,44.7 58.728,44.7 61.83,47.802 71.998,47.802 v1(72.3,47.5)
  Int3 w0.127: v1(72.3,47.5) 72.3,49.427 JDIGITAL.21@73.686,50.813
PH14: DOUT4.X J6.12 U1.B17 | length 37.2
  Top Layer w0.127: v1(20.26,26.48) 20.26,26.554 20.1,26.714 20.1,28.795 20.817,29.512 v1(22.974,29.512) ; v1(22.801,31.421) 22.811,31.412 23.502,31.412 25.167,33.077 25.167,33.669 25.929,34.431 25.929,34.977 27.994,37.042 31.198,37.042 31.526,37.371 33.309,37.371 33.926,37.988 35.676,37.988 35.951,37.713 35.951,35.101 36.14,34.912 36.14,34.367 U1.B17@36.126,34.353 ; J6.12@23.036,25.399 23.468,24.967 23.468,24.773 23.725,24.516 v1(23.774,24.516)
  Bottom Layer w0.127: v1(20.26,26.48) 22.843,26.48 23.774,25.549 v1(23.774,24.516) 24.499,24.516 25.382,25.399 DOUT4.X@26.862,25.399 ; v1(22.801,31.421) 22.801,31.347 22.974,31.174 v1(22.974,29.512)
PH15: JSIDE.27 U1.B16 | length 140.1
  Top Layer w0.127: v1(27.949,35.592) 27.942,35.586 27.942,34.297 27.489,33.843 27.1,33.843 26.904,34.039 26.904,34.362 26.972,34.43 26.972,35.526 27.819,36.374 30.037,36.374 30.858,35.553 32.155,35.553 32.254,35.454 33.02,35.454 34.333,34.142 34.935,34.142 35.111,33.966 35.713,33.966 U1.B16@36.126,33.553
  Int3 w0.127: v1(27.914,17.383) 27.914,17.388 26.755,18.547 26.755,19.4 25.682,20.472 25.682,25.403 26.047,25.768 26.406,26.127 26.406,29.033 27.494,30.12 27.494,31.227 27.823,31.557 27.823,33.475 27.949,33.6 v1(27.949,35.592) ; v1(89.686,6.511) 89.921,6.276 89.921,6.072 90.145,5.849 90.645,5.849 90.868,6.072 90.868,7.741 92.036,8.91 97.877,8.91 98.477,9.51 98.477,20.51 97.377,21.61 93.477,21.61 92.577,20.71 92.577,19.181 JSIDE.27@93.98,17.779
  Bottom Layer w0.127: v1(27.914,17.383) 28.233,17.064 29.784,17.064 29.914,16.933 29.914,13.513 34.245,9.183 35.304,9.183 36.415,10.294 42.72,10.294 42.992,10.565 46.559,10.565 ; 46.559,10.571 48.201,10.571 51.04,13.409 71.867,13.409 75.028,10.248 86.922,10.248 89.275,7.895 89.275,6.922 v1(89.686,6.511)
PI0: I2S2_WS.X J5.14 U1.A16 | length 99.5
  Top Layer w0.127: v1(27.362,34.884) 27.362,35.558 27.925,36.12 29.932,36.12 30.752,35.299 32.05,35.299 32.149,35.2 32.915,35.2 34.228,33.888 34.66,33.888 34.995,33.553 U1.A16@35.326,33.553 ; v1(75.12,22.227) 76.009,23.115 77.619,23.115 78.634,24.13 85.198,24.13 85.625,24.558 J5.14@85.625,25.399 86.145,25.399 86.925,24.619 v1(86.925,24.599)
  Int3 w0.127: v1(24.624,20.371) 24.281,20.713 23.71,20.713 23.419,21.004 23.419,21.616 24.157,22.354 24.157,22.528 24.895,23.266 24.895,25.693 25.285,26.084 ; 25.285,26.085 25.637,26.436 25.637,29.409 26.731,30.503 26.731,31.973 26.868,32.11 26.868,34.39 v1(27.362,34.884)
  Bottom Layer w0.127: v1(24.624,20.371) 24.813,20.56 24.877,20.56 25.105,20.788 25.105,20.852 25.279,21.026 27.132,21.026 27.983,20.174 29.525,20.174 30.769,18.93 32.456,18.93 34.546,16.84 37.22,16.84 37.609,17.229 43.367,17.229 43.435,17.162 44.988,17.162 45.064,17.237 48.714,17.237 48.766,17.185 50.291,17.185 51.108,18.002 53.549,18.002 54.593,16.959 56.343,16.959 61.313,21.929 74.6,21.929 74.86,22.188 75.082,22.188 v1(75.12,22.227) ; v1(86.925,24.599) 86.946,24.62 86.946,24.899 87.446,25.399 I2S2_WS.X@89.345,25.399
PI1: I2S2_CK.X J5.15 U1.A15 | length 92
  Top Layer w0.127: v1(25.947,33.704) 26.316,33.335 27.699,33.335 28.45,34.086 28.45,35.086 28.977,35.612 29.721,35.612 30.542,34.791 31.809,34.791 31.908,34.692 32.705,34.692 34.017,33.38 34.45,33.38 35.076,32.753 U1.A15@35.326,32.753 ; v1(75.627,21.889) 75.978,22.24 77.596,22.24 78.215,22.859 J5.15@79.825,22.859
  Int3 w0.127: v1(23.002,19.119) 23.002,21.558 23.821,22.377 23.821,22.552 24.641,23.371 24.641,25.798 25.031,26.189 25.031,26.688 24.856,26.863 24.856,27.856 25.383,28.383 25.383,29.514 26.477,30.608 26.477,32.542 25.947,33.073 v1(25.947,33.704)
  Bottom Layer w0.127: v1(23.002,19.119) 23.043,19.16 25.659,19.16 26.065,19.565 27.128,19.565 27.156,19.593 29.747,19.593 30.664,18.676 32.351,18.676 34.441,16.586 37.326,16.586 37.714,16.975 43.262,16.975 43.33,16.908 45.093,16.908 45.169,16.983 48.608,16.983 48.661,16.931 50.396,16.931 51.213,17.748 53.444,17.748 54.487,16.705 56.448,16.705 61.418,21.675 74.588,21.675 74.958,21.304 75.318,21.304 75.603,21.589 75.603,21.933 75.805,22.135 I2S2_CK.X@75.805,22.859
PI2: IS2S_SDI.X J5.16 U1.B15 | length 106
  Top Layer w0.127: v1(26.557,34.643) 26.557,34.027 26.994,33.589 27.594,33.589 28.196,34.191 28.196,35.191 28.872,35.866 29.826,35.866 30.647,35.045 31.914,35.045 32.013,34.946 32.81,34.946 34.123,33.634 34.555,33.634 35.011,33.177 35.552,33.177 35.702,33.177 U1.B15@36.126,32.753 ; v1(76.137,21.412) 76.484,21.759 85.225,21.759 85.625,22.159 J5.16@85.625,22.859 ; J5.16@86.145,22.859 v1@86.925,22.079
  Int3 w0.127: v1(22,19.488) 22.232,19.72 22.451,19.72 22.602,19.871 22.602,21.517 23.539,22.454 23.539,22.628 24.387,23.477 24.387,25.814 23.986,26.215 23.43,26.771 23.43,28.017 26.223,30.81 26.223,32.437 25.557,33.104 25.557,33.866 25.919,34.228 26.142,34.228 v1(26.557,34.643)
  Bottom Layer w0.127: v1(22,19.488) 22,18.968 22.24,18.728 23.552,18.728 23.729,18.906 25.764,18.906 26.17,19.311 29.67,19.311 30.559,18.422 32.246,18.422 34.336,16.332 37.431,16.332 37.82,16.721 43.157,16.721 43.224,16.654 45.199,16.654 45.274,16.729 48.503,16.729 48.556,16.677 50.501,16.677 51.319,17.494 53.339,17.494 54.42,16.413 56.569,16.413 61.577,21.421 74.482,21.421 74.853,21.05 75.739,21.05 76.101,21.412 v1(76.137,21.412) ; v1(86.925,22.059) 86.946,22.08 86.946,22.359 87.446,22.859 IS2S_SDI.X@89.345,22.859
PI3: I2S2_SDO.X J5.17 U1.C14 | length 111.8
  Top Layer w0.127: U1.C14@36.926,31.953 v1(37.326,32.353) ; v1(76.382,19.733) 76.968,20.319 J5.17@79.525,20.319
  Int3 w0.127: v1(19.923,14.395) 19.143,14.395 18.871,14.123 18.464,14.123 17.602,14.986 17.602,18.119 18.348,18.865 19.623,18.865 20.066,19.307 20.066,21.513 20.212,21.659 22.384,21.659 23.285,22.559 23.285,24.353 22.631,25.007 22.631,27.578 25.826,30.773 25.826,32.282 v1(25.822,32.286)
  Bottom Layer w0.127: v1(19.923,14.395) 19.997,14.395 20.085,14.307 21.962,14.307 22.457,14.801 22.457,17.274 23.834,18.652 25.937,18.652 26.342,19.057 29.565,19.057 30.454,18.168 32.141,18.168 34.231,16.078 37.536,16.078 37.925,16.467 43.052,16.467 43.119,16.4 45.304,16.4 45.379,16.475 48.398,16.475 48.451,16.423 50.607,16.423 51.424,17.24 53.234,17.24 54.333,16.14 56.682,16.14 61.709,21.167 74.377,21.167 75.205,20.339 75.785,20.339 I2S2_SDO.X@75.805,20.319 76.382,19.742 v1(76.382,19.733) ; v1(25.822,32.286) 24.628,32.286 24.1,32.814 24.1,33.197 24.998,34.095 26.987,34.095 27.198,33.884 28.074,33.884 28.235,34.045 30.535,34.045 31.245,33.336 31.415,33.336 32.125,32.626 32.754,32.626 32.966,32.838 36.71,32.838 37.059,32.489 37.116,32.489 37.252,32.353 v1(37.326,32.353)
PI4: DOUT5.X J6.11 U1.A4 | length 30.1
  Top Layer w0.127: J6.11@17.042,25.399 v1(17.042,26.342) ; J6.11@17.342,25.399 18.115,26.172 18.605,26.172 18.777,26.345 19.05,26.345 v1(19.063,26.358) ; v1(25.246,27.026) 25.285,26.987 25.285,26.532 25.984,25.833 25.984,23.086 27.542,21.528 30.289,21.528 30.827,22.066 32.339,22.066 32.876,22.603 32.876,23.055 33.266,23.445 33.459,23.638 33.539,23.638 34.347,23.639 34.663,23.955 U1.A4@35.326,23.953
  Bottom Layer w0.127: DOUT5.X@13.322,25.399 14.266,26.342 v1(17.042,26.342) ; v1(19.063,26.358) 19.576,26.871 23.134,26.871 23.869,26.136 24.931,26.136 25.246,26.451 v1(25.246,27.026)
PI5: J6.5 U1.A3 VSYNC.X | length 32.7
  Top Layer w0.127: J6.5@17.468,33.019 17.603,32.884 17.603,32.393 v1(18.071,31.924) ; v1(24.567,28.601) 24.856,28.312 24.856,26.863 25.031,26.688 25.031,26.426 25.701,25.757 25.701,22.969 27.396,21.274 30.402,21.274 30.94,21.812 33.121,21.812 33.175,21.758 34.033,21.758 34.414,22.139 34.414,22.447 35.085,23.117 35.291,23.117 U1.A3@35.326,23.153
  Bottom Layer w0.127: VSYNC.X@13.322,33.019 13.824,32.517 17.56,32.517 17.963,32.114 17.963,32.107 18.071,31.998 v1(18.071,31.924) 21.331,31.924 22.584,30.672 22.584,29.35 23.333,28.601 v1(24.567,28.601)
PI6: DOUT6.X J6.10 U1.A2 | length 21.8
  Top Layer w0.127: J6.10@22.842,27.939 23.692,27.939 23.915,27.715 23.915,27.234 23.836,27.154 v1(23.836,27.08) 24.157,26.759 24.157,26.389 25.102,25.444 25.102,22.768 27.104,20.766 30.613,20.766 31.151,21.304 32.911,21.304 32.965,21.25 34.243,21.25 34.951,21.957 34.951,21.977 U1.A2@35.326,22.353
  Bottom Layer w0.127: v1(23.836,27.08) 23.836,27.085 24.313,27.562 24.769,27.562 25.126,27.919 26.842,27.919 DOUT6.X@26.862,27.939
PI7: DOUT7.X J6.9 U1.B3 | length 29.5
  Top Layer w0.127: J6.9@17.042,27.939 v1(17.042,28.842) ; J6.9@17.342,27.939 18.108,27.172 18.63,27.172 18.804,26.997 19.023,26.997 v1(19.063,26.958) ; v1(24.572,26.526) 25.418,25.681 25.418,22.852 27.25,21.02 30.508,21.02 31.046,21.558 33.016,21.558 33.07,21.504 34.138,21.504 34.697,22.062 34.697,22.255 35.171,22.728 35.702,22.728 U1.B3@36.126,23.153
  Bottom Layer w0.127: DOUT7.X@13.322,27.939 14.226,28.842 v1(17.042,28.842) ; v1(19.063,26.958) 19.115,27.01 19.356,27.01 19.471,27.125 23.239,27.125 23.838,26.526 v1(24.572,26.526)
PI8: U1.E4 U5.27 WIFI_HWAKE.X | length 95.7
  Top Layer w0.127: v1(13.915,46.29) U5.27@13.915,46.99 ; U1.E4@38.526,23.953 v1(38.926,23.553)
  Int3 w0.127: v1(13.915,46.29) 14.51,45.695 15.767,45.695 16.639,44.822 16.639,43.449 16.034,42.844 16.034,40.091 14.874,38.931 14.874,20.921 15.312,20.483 v1(15.312,17.342) ; v1(38.086,6.677) 38.038,6.725 38.038,7.035 38.034,7.038 38.034,7.393 38.595,7.953 38.595,9.392 40.506,11.304 40.506,21.157 41.717,22.368 41.717,22.934 41.488,23.162 40.247,23.162 40.117,23.293 40.117,23.715 39.888,23.943 39.564,23.943 39.199,23.578 38.951,23.578 v1(38.926,23.553)
  Bottom Layer w0.127: v1(15.312,17.342) 15.312,15.68 18.193,12.799 18.34,12.799 19.512,11.627 19.512,8.139 20.001,7.65 21.344,7.65 WIFI_HWAKE.X@21.362,7.633 21.178,7.449 21.178,5.834 22.248,4.764 24.356,4.764 25.7,3.42 25.7,2.3 26.7,1.3 38.884,1.3 39.303,1.72 39.303,5.002 38.086,6.219 v1(38.086,6.677)
PI9: JDIGITAL.22 U1.E2 | length 75.6
  Top Layer w0.127: v1(37.954,18.678) 37.954,18.752 37.812,18.893 37.812,19.138 38.936,20.261 38.936,21.943 38.926,21.953 U1.E2@38.526,22.353 ; v1(59.716,49.478) 60.014,49.18 74.593,49.18 JDIGITAL.22@76.226,50.813
  Int3 w0.127: v1(59.716,49.478) 59.716,49.462 59.894,49.283 59.894,48.211 59.753,48.07 59.753,47.055 60.866,45.942 60.866,24.013 v1(61.466,23.413)
  Bottom Layer w0.127: v1(37.954,18.678) 37.954,18.616 38.833,17.737 43.578,17.737 43.645,17.67 43.983,17.67 44.544,18.23 44.884,18.23 45.369,17.745 48.924,17.745 48.977,17.693 50.047,17.693 53.296,20.942 54.898,20.942 55.68,21.724 58.677,21.724 59.866,22.913 61.304,22.913 61.466,23.074 v1(61.466,23.413)
PI10: JSIDE.24 U1.F3 | length 92.7
  Top Layer w0.127: U1.F3@39.326,23.153 v1(39.726,22.753)
  Int2 w0.127: v1(35.224,11.729) 35.261,11.692 37.098,11.692 37.547,11.244 45.79,11.244 47.695,9.339 52.307,9.339 55.492,12.524 66.865,12.524 70.549,8.841 89.125,8.841 91.599,11.314 91.599,22.297 93.43,24.129 95.25,24.129 JSIDE.24@96.52,22.859
  Int3 w0.127: v1(35.224,11.729) 35,11.953 35,12.888 36.277,14.164 36.277,18.804 37.251,19.778 37.251,21.283 37.568,21.6 38.685,21.6 39.571,22.486 39.571,22.524 39.726,22.679 v1(39.726,22.753)
PI11: JSIDE.31 U1.F4 | length 92.8
  Top Layer w0.127: U1.F4@39.326,23.953 v1(39.726,23.553)
  Int2 w0.127: v1(34.705,11.05) 36.989,11.05 37.304,10.735 45.471,10.735 47.375,8.831 52.521,8.831 55.66,11.97 66.701,11.97 70.338,8.333 90.755,8.333 92.835,6.253 97.726,6.253 97.9,6.427 97.9,10.778 97.226,11.453 95.226,11.453 JSIDE.31@93.98,12.699
  Int3 w0.127: v1(34.705,11.05) 34.705,11.124 34.6,11.229 34.6,12.567 34.746,12.713 34.746,12.993 36.007,14.254 36.007,18.933 36.997,19.924 36.997,21.424 37.428,21.854 38.58,21.854 39.317,22.591 39.317,23.143 v1(39.726,23.553)
PI12: R11.2 RED.X U1.H1 | length 64.6
  Top Layer w0.127: R11.2@10.375,1 v1(11.1,1) ; v1(37.877,18.132) 37.951,18.132 38.106,18.287 38.116,18.287 38.285,18.457 38.285,18.46 38.36,18.535 38.36,19.238 39.222,20.1 40.341,20.1 40.926,20.685 U1.H1@40.926,21.553
  Int2 w0.127: v1(11.1,1) 10.2,1 9.75,1.45 9.75,6.95 10.572,7.772 12.777,7.772 13.739,6.81 21.06,6.81 21.432,7.182 21.92,7.182 22.085,7.017 v1(22.127,7.017)
  Int3 w0.127: v1(22.127,7.017) 22.65,7.54 22.65,10.184 22.396,10.438 22.396,13.244 22.44,13.288 22.44,13.612 23.993,15.165 23.993,19.293 v1(24.25,19.55)
  Bottom Layer w0.127: RED.X@6.122,2.553 7.125,1.549 10.551,1.549 v1(11.1,1) ; v1(24.25,19.55) 23.05,20.75 23.05,21.25 23.567,21.767 24.47,21.767 24.681,21.555 27.31,21.555 27.335,21.531 27.344,21.531 28.193,20.682 29.736,20.682 30.98,19.438 32.725,19.438 34.173,17.991 36.618,17.991 36.759,18.132 v1(37.877,18.132)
